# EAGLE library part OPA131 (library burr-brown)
Operational Amplifiers General Purpose FET-Input
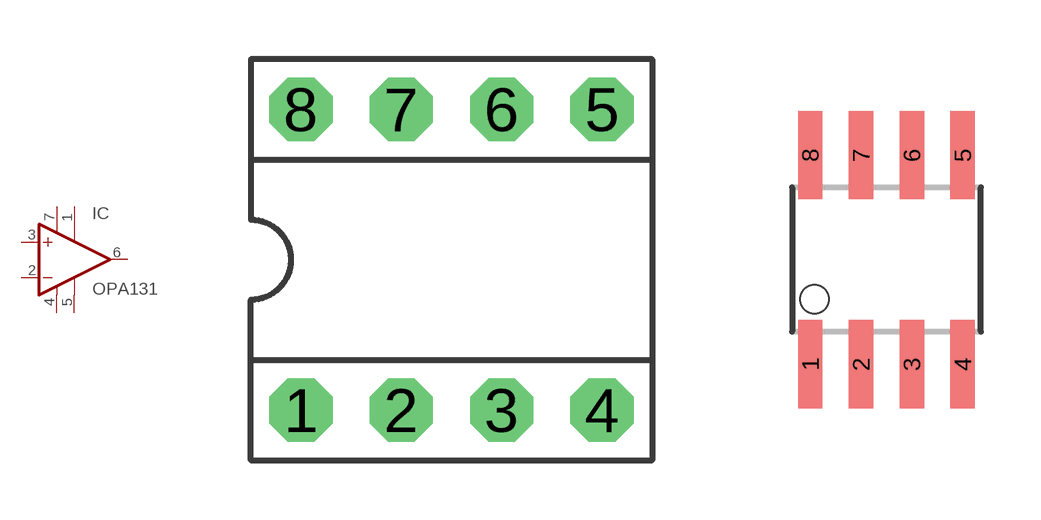
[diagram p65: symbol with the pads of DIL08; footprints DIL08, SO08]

Designator prefix IC

## OPA131P (OC_FARNELL: unknown; OC_NEWARK: unknown)  [DIL08]
1  TRIM1  pas
2  -IN  in
3  +IN  in
4  V-  pwr
5  TRIM2  pas
6  OUT  out
7  V+  pwr

## OPA131U (MF: TEXAS INSTRUMENT CONNECTORS; MPN: OPA131U; OC_FARNELL: 1459547; OC_NEWARK: 75C4591)  [SO08]
Pads as for DIL08

## Footprint DIL08 (pad centres in mm)
Dual In Line
drill 0.813 pad 1.6 octagon: 1 -3.81,-3.81; 2 -1.27,-3.81; 3 1.27,-3.81; 4 3.81,-3.81; 5 3.81,3.81; 6 1.27,3.81; 7 -1.27,3.81; 8 -3.81,3.81

## Footprint SO08 (pad centres in mm)
Small Outline Package
smd 0.61 x 2.21: 1 -1.905,-2.616; 2 -0.635,-2.616; 3 0.635,-2.616; 4 1.905,-2.616; 5 1.905,2.616; 6 0.635,2.616; 7 -0.635,2.616; 8 -1.905,2.616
